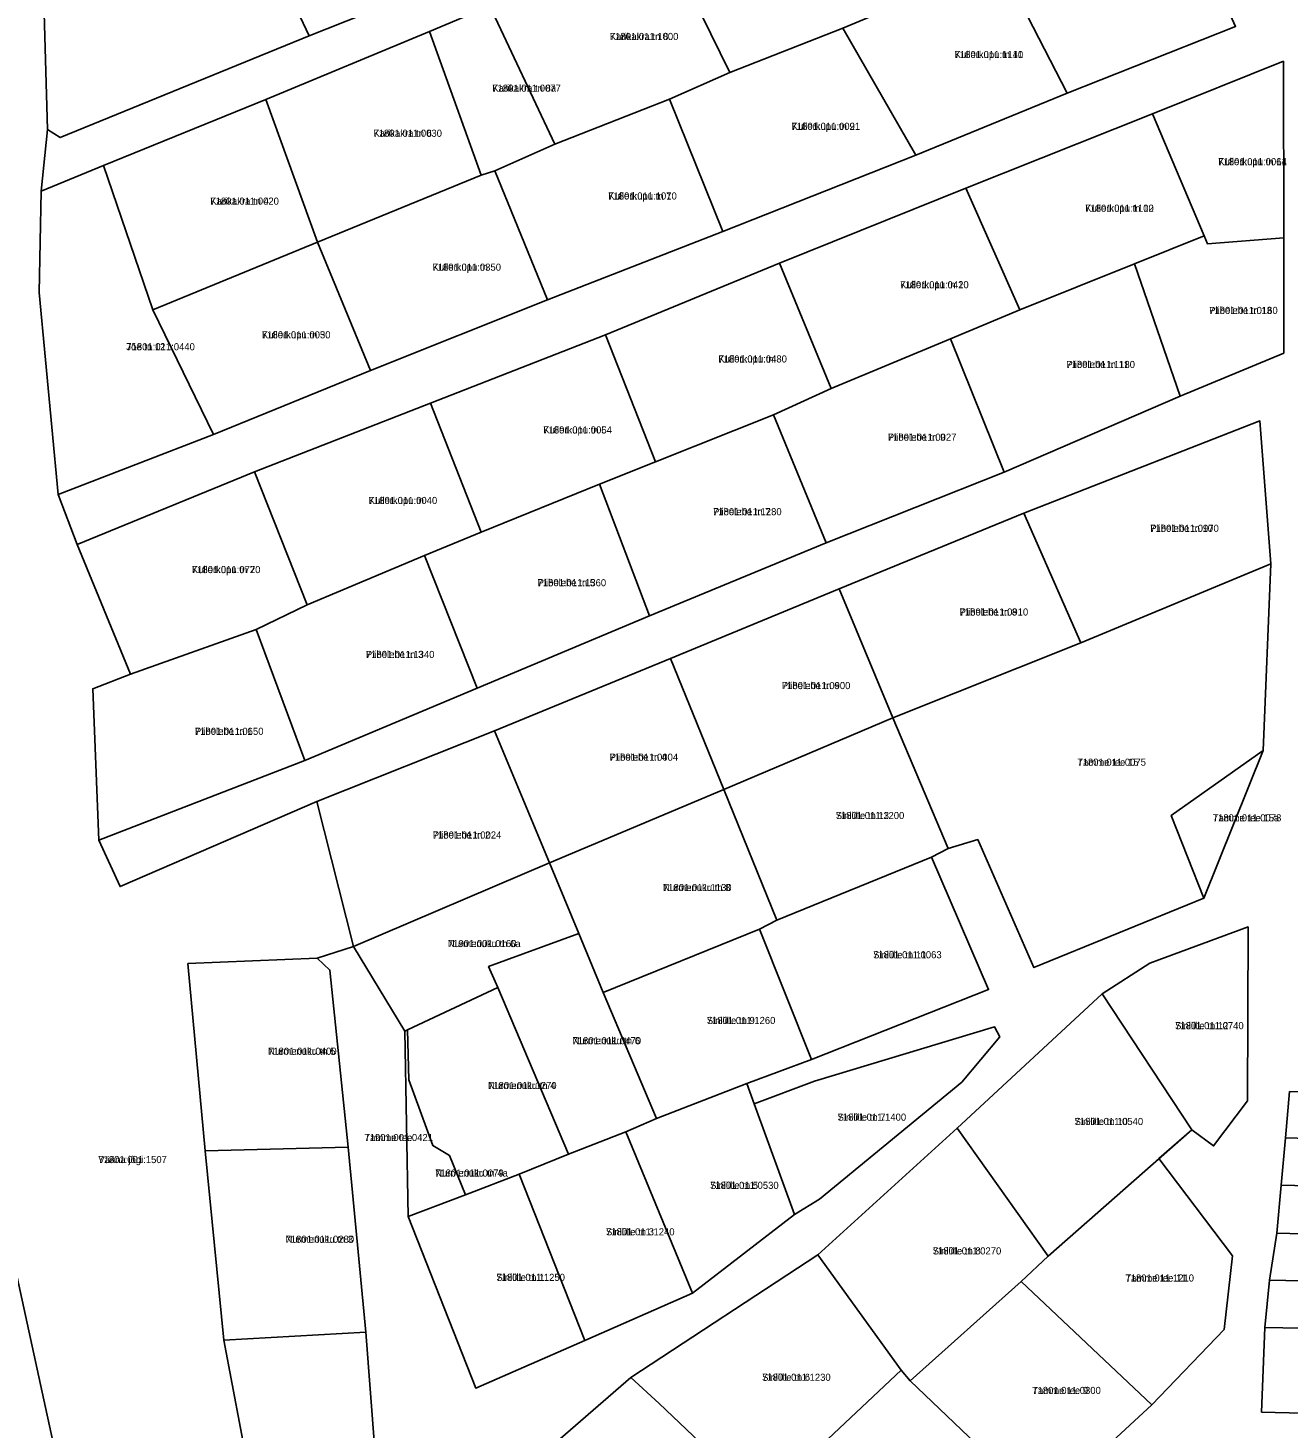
# Model space of a CAD drawing. Extents: x 529768 to 552006, y 6562269 to 6580975.
# Drawn here: x 537900.7 to 538167.2, y 6574495.4 to 6574791.4 of the extents above; entities that cross this region are included whole.
import ezdxf

# ---------------------------------------------------------------- set-up
doc = ezdxf.new("R2010")
doc.units = 0
for name, color, linetype in [('L_AADRESS', 7, 'Continuous'), ('PIIR', 7, 'Continuous'), ('TUNNUS', 7, 'Continuous')]:
    doc.layers.add(name, color=color, linetype=linetype)

msp = doc.modelspace()

# ---------------------------------------------------------------- linework, layer by layer
at = {"layer": 'PIIR'}
for points in [[(537946.52, 6574818.64), (537981.35, 6574832.85), (537995.22, 6574803.73), (537960.16, 6574789.77)], [(538085.22, 6574796.45), (538073.06, 6574791.35), (538049.15, 6574782), (538034.99, 6574810.89), (538071.56, 6574824.72)], [(538106.12, 6574805.6), (538120.62, 6574811.91), (538142.63, 6574821.49), (538156.07, 6574791.75), (538120.48, 6574777.61)], [(537960.16, 6574789.77), (537907.52, 6574768.22), (537904.83, 6574769.93), (537903.95, 6574801.98), (537911.06, 6574804.7), (537944.5, 6574817.88), (537946.52, 6574818.64)], [(538034.99, 6574810.89), (538049.15, 6574782), (538036.39, 6574776.37), (538012.14, 6574766.84), (537998.37, 6574795.99)], [(538088.44, 6574764.5), (538073.06, 6574791.35), (538085.22, 6574796.45), (538106.12, 6574805.6), (538120.48, 6574777.61)], [(537998.37, 6574795.99), (538012.14, 6574766.84), (537999.43, 6574761.17), (537996.55, 6574760.29), (537985.66, 6574790.65)], [(538088.44, 6574764.5), (538047.66, 6574748.39), (538036.39, 6574776.37), (538049.15, 6574782), (538073.06, 6574791.35)], [(537961.93, 6574746.14), (537951, 6574776.32), (537985.66, 6574790.65), (537996.55, 6574760.29)], [(538138.52, 6574773.26), (538166.19, 6574784.37), (538166.29, 6574747.06), (538150.16, 6574745.76), (538149.46, 6574747.46)], [(537927.1, 6574731.79), (537916.67, 6574762.36), (537951, 6574776.32), (537961.93, 6574746.14)], [(537999.43, 6574761.17), (538012.14, 6574766.84), (538036.39, 6574776.37), (538047.66, 6574748.39), (538010.58, 6574733.91)], [(538099.03, 6574757.55), (538138.52, 6574773.26), (538149.46, 6574747.46), (538134.72, 6574741.53), (538110.48, 6574731.84)], [(537903.06, 6574735.44), (537903.5, 6574756.9), (537916.67, 6574762.36), (537927.1, 6574731.79), (537939.95, 6574705.42), (537907.1, 6574692.78)], [(537973.17, 6574718.98), (537961.93, 6574746.14), (537996.55, 6574760.29), (537999.43, 6574761.17), (538010.58, 6574733.91)], [(538059.65, 6574741.7), (538099.03, 6574757.55), (538110.48, 6574731.84), (538095.8, 6574725.71), (538070.54, 6574715.19)], [(538144.39, 6574713.55), (538134.72, 6574741.53), (538149.46, 6574747.46), (538150.16, 6574745.76), (538166.29, 6574747.06), (538166.27, 6574722.66)], [(537939.95, 6574705.42), (537927.1, 6574731.79), (537961.93, 6574746.14), (537973.17, 6574718.98)], [(538033.39, 6574699.64), (538022.82, 6574726.53), (538059.65, 6574741.7), (538070.54, 6574715.19), (538058.39, 6574709.61)], [(538095.8, 6574725.71), (538110.48, 6574731.84), (538134.72, 6574741.53), (538144.39, 6574713.55), (538107.13, 6574697.48)], [(538033.39, 6574699.64), (538021.57, 6574694.92), (537996.56, 6574684.79), (537985.83, 6574712.06), (538022.82, 6574726.53)], [(538058.39, 6574709.61), (538070.54, 6574715.19), (538095.8, 6574725.71), (538107.13, 6574697.48), (538069.51, 6574682.55)], [(537959.78, 6574669.45), (537948.62, 6574697.53), (537985.83, 6574712.06), (537996.56, 6574684.79), (537984.6, 6574679.87)], [(538021.57, 6574694.92), (538033.39, 6574699.64), (538058.39, 6574709.61), (538069.51, 6574682.55), (538032.16, 6574667.12)], [(538111.33, 6574688.8), (538161.23, 6574708.32), (538163.52, 6574678.07), (538123.39, 6574661.39)], [(537911.11, 6574682.19), (537948.62, 6574697.53), (537959.78, 6574669.45), (537948.94, 6574664.21), (537922.42, 6574654.73)], [(537984.6, 6574679.87), (537996.56, 6574684.79), (538021.57, 6574694.92), (538032.16, 6574667.12), (537995.69, 6574651.8)], [(538072.26, 6574672.82), (538111.33, 6574688.8), (538123.39, 6574661.39), (538083.58, 6574645.52)], [(537948.94, 6574664.21), (537959.78, 6574669.45), (537984.6, 6574679.87), (537995.69, 6574651.8), (537959.25, 6574636.5)], [(538083.58, 6574645.52), (538123.39, 6574661.39), (538163.52, 6574678.07), (538161.94, 6574638.6), (538142.43, 6574624.87), (538149.4, 6574607.43), (538113.44, 6574592.72), (538101.55, 6574619.77), (538095.33, 6574617.87)], [(538036.56, 6574658.07), (538072.26, 6574672.82), (538083.58, 6574645.52), (538047.87, 6574630.38)], [(537914.42, 6574651.67), (537922.42, 6574654.73), (537948.94, 6574664.21), (537959.25, 6574636.5), (537915.72, 6574619.64)], [(537999.38, 6574642.8), (538036.56, 6574658.07), (538047.87, 6574630.38), (538010.97, 6574614.85)], [(538047.87, 6574630.38), (538083.58, 6574645.52), (538095.33, 6574617.87), (538091.8, 6574616.1), (538059.05, 6574602.74)], [(537961.83, 6574627.84), (537999.38, 6574642.8), (538010.97, 6574614.85), (537969.54, 6574597.19)], [(538142.43, 6574624.87), (538161.94, 6574638.6), (538149.4, 6574607.43)], [(538017.17, 6574599.89), (538010.97, 6574614.85), (538047.87, 6574630.38), (538059.05, 6574602.74), (538055.38, 6574600.81), (538022.32, 6574587.43)], [(537980.98, 6574579.52), (537980.41, 6574579.25), (537969.54, 6574597.19), (538010.97, 6574614.85), (538017.17, 6574599.89), (537998.11, 6574592.93), (538000.07, 6574588.52)], [(538091.8, 6574616.1), (538103.87, 6574588.05), (538066.43, 6574573.26), (538055.38, 6574600.81), (538059.05, 6574602.74)], [(537996.82, 6574478.82), (537997.54, 6574472.97), (537973.58, 6574445.13), (537997.53, 6574424.08), (538027.06, 6574397.05), (538048.62, 6574417.12), (538070.93, 6574438.07), (538093.3, 6574458.58), (538115.08, 6574478.77), (538138.41, 6574500.28), (538153.66, 6574516.15), (538155.46, 6574531.75), (538139.89, 6574552.36), (538146.85, 6574558.4), (538151.43, 6574555.01), (538158.6, 6574564.51), (538158.74, 6574601.33), (538137.96, 6574593.64), (538127.87, 6574587.14), (538097.2, 6574558.77), (538067.76, 6574531.97), (538028.22, 6574506.01)], [(537998.11, 6574592.93), (538017.17, 6574599.89), (538022.32, 6574587.43), (538033.62, 6574560.77), (538027.13, 6574558), (538015.02, 6574553.28), (538000.07, 6574588.52)], [(538022.32, 6574587.43), (538055.38, 6574600.81), (538066.43, 6574573.26), (538052.76, 6574568.17), (538033.62, 6574560.77)], [(538137.96, 6574593.64), (538158.74, 6574601.33), (538158.6, 6574564.51), (538151.43, 6574555.01), (538146.85, 6574558.4), (538127.87, 6574587.14)], [(537934.55, 6574593.57), (537961.9, 6574594.68), (537964.55, 6574592.18), (537968.41, 6574554.74), (537938.2, 6574553.94)], [(537980.98, 6574579.52), (538000.07, 6574588.52), (538015.02, 6574553.28), (538004.62, 6574549.06), (537993.21, 6574544.69), (537989.85, 6574553.01), (537986.35, 6574555.08), (537981.24, 6574569.01)], [(538097.2, 6574558.77), (538127.87, 6574587.14), (538146.85, 6574558.4), (538116.48, 6574531.71)], [(537980.41, 6574579.25), (537980.98, 6574579.52), (537981.24, 6574569.01), (537986.35, 6574555.08), (537989.85, 6574553.01), (537993.21, 6574544.69), (537981.08, 6574540.05)], [(538054.31, 6574563.89), (538067.05, 6574568.68), (538105.07, 6574580.21), (538106.22, 6574578.08), (538098.2, 6574568.52), (538068.07, 6574543.76), (538062.78, 6574540.47)], [(538027.13, 6574558), (538033.62, 6574560.77), (538052.76, 6574568.17), (538054.31, 6574563.89), (538062.78, 6574540.47), (538041.27, 6574523.83)], [(538167.5, 6574566.52), (538189.87, 6574565.98), (538209.2, 6574565.42), (538208.92, 6574555.53), (538166.62, 6574556.69)], [(538004.62, 6574549.06), (538015.03, 6574553.26), (538027.13, 6574558), (538041.27, 6574523.83), (538018.46, 6574513.87)], [(538067.76, 6574531.97), (538097.2, 6574558.77), (538116.48, 6574531.71), (538110.73, 6574526.33), (538087.27, 6574505.33), (538085.34, 6574507.58)], [(537938.2, 6574553.94), (537968.41, 6574554.74), (537972.15, 6574515.6), (537942.13, 6574513.92)], [(538208.92, 6574555.53), (538208.89, 6574554.47), (538208.66, 6574545.68), (538165.72, 6574546.67), (538166.62, 6574556.69)], [(538110.73, 6574526.33), (538116.48, 6574531.71), (538139.89, 6574552.36), (538155.46, 6574531.75), (538153.66, 6574516.15), (538138.41, 6574500.28)], [(537981.08, 6574540.05), (537993.21, 6574544.69), (538004.62, 6574549.06), (538018.46, 6574513.87), (537995.42, 6574503.81)], [(538208.66, 6574545.68), (538208.34, 6574535.42), (538164.83, 6574536.58), (538165.72, 6574546.67)], [(538163.23, 6574526.6), (538164.83, 6574536.58), (538208.34, 6574535.42), (538207.99, 6574525.72)], [(538028.22, 6574506.01), (538067.76, 6574531.97), (538085.34, 6574507.58), (538066.31, 6574489.65), (538067.55, 6574488.41), (538064.58, 6574485.79), (538057.15, 6574478.7), (538034.16, 6574500.56)], [(538087.27, 6574505.33), (538110.73, 6574526.33), (538138.41, 6574500.28), (538115.08, 6574478.77)], [(538162.24, 6574516.63), (538163.23, 6574526.6), (538207.99, 6574525.72), (538207.6, 6574515.74)], [(537942.13, 6574513.92), (537972.15, 6574515.6), (537976, 6574465.87), (537963.82, 6574455.16), (537950.92, 6574467.42)], [(538207.24, 6574503.12), (538208.48, 6574502.05), (538205.17, 6574497.62), (538161.6, 6574498.73), (538162.24, 6574516.63), (538207.6, 6574515.74)], [(538066.31, 6574489.65), (538085.34, 6574507.58), (538087.27, 6574505.33), (538115.08, 6574478.77), (538093.3, 6574458.58), (538064.58, 6574485.79), (538067.55, 6574488.41)], [(537996.82, 6574478.82), (538028.22, 6574506.01), (538034.16, 6574500.56), (538057.15, 6574478.7), (538042.38, 6574464.77), (538026.52, 6574450.97), (537997.54, 6574472.97)]]:
    msp.add_lwpolyline(points, close=True, dxfattribs=at)
for points in [[(537877.44, 6574804.07), (537877.38, 6574790.27), (537879.6, 6574679.21), (537880.42, 6574620.55), (537883.61, 6574583.23), (537894.34, 6574545.71), (537908.44, 6574481.23)], [(537954.55, 6574169.98), (537951.1, 6574224.38), (537959.6, 6574242.27), (537930.27, 6574387.38), (537908.44, 6574481.23), (537894.34, 6574545.71), (537883.61, 6574583.23), (537880.42, 6574620.55), (537879.6, 6574679.21), (537877.38, 6574790.27), (537877.44, 6574804.07)], [(537998.37, 6574795.99), (537985.66, 6574790.65), (537951, 6574776.32), (537916.67, 6574762.36), (537903.5, 6574756.9), (537904.83, 6574769.93), (537907.52, 6574768.22), (537960.16, 6574789.77), (537995.22, 6574803.73)], [(537903.95, 6574801.98), (537904.83, 6574769.93), (537903.5, 6574756.9), (537903.06, 6574735.44), (537907.1, 6574692.78), (537911.11, 6574682.19), (537922.42, 6574654.73), (537914.42, 6574651.67), (537915.72, 6574619.64), (537920.2, 6574609.84), (537961.83, 6574627.84), (537969.54, 6574597.19), (537961.9, 6574594.68), (537934.55, 6574593.57), (537938.2, 6574553.94), (537942.13, 6574513.92), (537950.92, 6574467.42)], [(537976, 6574465.87), (537972.15, 6574515.6), (537968.41, 6574554.74), (537964.55, 6574592.18), (537961.9, 6574594.68), (537969.54, 6574597.19), (537980.41, 6574579.25), (537981.08, 6574540.05), (537995.42, 6574503.81), (538018.46, 6574513.87), (538041.27, 6574523.83), (538062.78, 6574540.47), (538068.07, 6574543.76), (538098.2, 6574568.52), (538106.22, 6574578.08), (538105.07, 6574580.21), (538067.05, 6574568.68), (538054.31, 6574563.89), (538052.76, 6574568.17), (538066.43, 6574573.26), (538103.87, 6574588.05), (538091.8, 6574616.1), (538095.33, 6574617.87), (538101.55, 6574619.77), (538113.44, 6574592.72), (538149.4, 6574607.43), (538161.94, 6574638.6), (538163.52, 6574678.07), (538161.23, 6574708.32), (538111.33, 6574688.8), (538072.26, 6574672.82), (538036.56, 6574658.07), (537999.38, 6574642.8), (537961.83, 6574627.84), (537920.2, 6574609.84), (537915.72, 6574619.64), (537959.25, 6574636.5), (537995.69, 6574651.8), (538032.16, 6574667.12), (538069.51, 6574682.55), (538107.13, 6574697.48), (538144.39, 6574713.55), (538166.27, 6574722.66), (538166.29, 6574747.06), (538166.19, 6574784.37), (538138.52, 6574773.26), (538099.03, 6574757.55), (538059.65, 6574741.7), (538022.82, 6574726.53), (537985.83, 6574712.06), (537948.62, 6574697.53), (537911.11, 6574682.19), (537907.1, 6574692.78), (537939.95, 6574705.42), (537973.17, 6574718.98), (538010.58, 6574733.91), (538047.66, 6574748.39), (538088.44, 6574764.5), (538120.48, 6574777.61), (538156.07, 6574791.75)], [(538167.5, 6574566.52), (538166.62, 6574556.69), (538165.72, 6574546.67), (538164.83, 6574536.58), (538163.23, 6574526.6), (538162.24, 6574516.63), (538161.6, 6574498.73), (538205.17, 6574497.62)]]:
    msp.add_lwpolyline(points, dxfattribs=at)

# ---------------------------------------------------------------- texts
at = {"layer": 'L_AADRESS'}
for s, p in [('Karikakra tn 8', (538023.76, 6574788.87)), ('Kullerkupu tn 11', (538096.67, 6574785.05)), ('Karikakra tn 8a', (537998.9, 6574777.94)), ('Kullerkupu tn 9', (538062.19, 6574769.87)), ('Karikakra tn 6', (537973.76, 6574768.4)), ('Kullerkupu tn 14', (538152.41, 6574762.39)), ('Karikakra tn 4', (537939.28, 6574754.05)), ('Kullerkupu tn 7', (538023.42, 6574755.14)), ('Kullerkupu tn 12', (538124.28, 6574752.55)), ('Kullerkupu tn 5', (537986.25, 6574740.08)), ('Kullerkupu tn 10', (538085.15, 6574736.37)), ('Piibelehe tn 13', (538150.5, 6574730.94)), ('Kullerkupu tn 3', (537950.19, 6574725.78)), ('Jõe tn 12', (537921.51, 6574723.26)), ('Kullerkupu tn 8', (538046.71, 6574720.67)), ('Piibelehe tn 11', (538120.31, 6574719.51)), ('Kullerkupu tn 6', (538009.69, 6574705.66)), ('Piibelehe tn 9', (538082.55, 6574704.13)), ('Kullerkupu tn 4', (537972.76, 6574690.75)), ('Piibelehe tn 7', (538045.59, 6574688.37)), ('Piibelehe tn 10', (538138.04, 6574684.86)), ('Kullerkupu tn 2', (537935.37, 6574676.13)), ('Piibelehe tn 5', (538008.48, 6574673.36)), ('Piibelehe tn 8', (538097.73, 6574667.16)), ('Piibelehe tn 3', (537972.17, 6574658.19)), ('Piibelehe tn 6', (538060.13, 6574651.6)), ('Piibelehe tn 1', (537936.02, 6574641.93)), ('Piibelehe tn 4', (538023.7, 6574636.46)), ('Tamme tee 15', (538122.63, 6574635.4)), ('Sinilille tn 13', (538071.53, 6574624.13)), ('Tamme tee 15a', (538151.26, 6574623.63)), ('Piibelehe tn 2', (537986.32, 6574620)), ('Nurmenuku tn 8', (538035, 6574608.9)), ('Nurmenuku tn 6a', (537989.51, 6574597.05)), ('Sinilille tn 11', (538079.43, 6574594.68)), ('Sinilille tn 9', (538044.27, 6574580.79)), ('Sinilille tn 12', (538143.3, 6574579.69)), ('Nurmenuku tn 6', (538015.86, 6574576.51)), ('Nurmenuku tn 5', (537951.48, 6574574.27)), ('Nurmenuku tn 4', (537998, 6574567.03)), ('Sinilille tn 7', (538071.92, 6574560.34)), ('Sinilille tn 10', (538122.04, 6574559.43)), ('Tamme tee', (537971.86, 6574556.03)), ('Vääna jõgi', (537915.59, 6574551.37)), ('Nurmenuku tn 4a', (537986.81, 6574548.52)), ('Sinilille tn 5', (538044.96, 6574545.92)), ('Sinilille tn 3', (538022.95, 6574536.09)), ('Nurmenuku tn 3', (537955.18, 6574534.52)), ('Sinilille tn 8', (538092.04, 6574532.05)), ('Sinilille tn 1', (537999.77, 6574526.46)), ('Tamme tee 11', (538132.79, 6574526.32)), ('Sinilille tn 6', (538055.96, 6574505.33)), ('Tamme tee 9', (538113.09, 6574502.55))]:
    msp.add_text(s, height=1.5, dxfattribs=at).set_placement(p)
at = {"layer": 'TUNNUS'}
for s, p in [('71801:011:1000', (538023.76, 6574788.87)), ('71801:011:1140', (538096.67, 6574785.05)), ('71801:011:0077', (537998.9, 6574777.94)), ('71801:011:0021', (538062.19, 6574769.87)), ('71801:011:0030', (537973.76, 6574768.4)), ('71801:011:0061', (538152.41, 6574762.39)), ('71801:011:0020', (537939.28, 6574754.05)), ('71801:011:1010', (538023.42, 6574755.14)), ('71801:011:1100', (538124.28, 6574752.55)), ('71801:011:0350', (537986.25, 6574740.08)), ('71801:011:0420', (538085.15, 6574736.37)), ('71801:011:0160', (538150.5, 6574730.94)), ('71801:011:0050', (537950.19, 6574725.78)), ('71801:011:0440', (537921.51, 6574723.26)), ('71801:011:0430', (538046.71, 6574720.67)), ('71801:011:1180', (538120.31, 6574719.51)), ('71801:011:0054', (538009.69, 6574705.66)), ('71801:011:0027', (538082.55, 6574704.13)), ('71801:011:0040', (537972.76, 6574690.75)), ('71801:011:1280', (538045.59, 6574688.37)), ('71801:011:0970', (538138.04, 6574684.86)), ('71801:011:0770', (537935.37, 6574676.13)), ('71801:011:1360', (538008.48, 6574673.36)), ('71801:011:0910', (538097.73, 6574667.16)), ('71801:011:1340', (537972.17, 6574658.19)), ('71801:011:0900', (538060.13, 6574651.6)), ('71801:011:0650', (537936.02, 6574641.93)), ('71801:011:0004', (538023.7, 6574636.46)), ('71801:011:0075', (538122.63, 6574635.4)), ('71801:011:1200', (538071.53, 6574624.13)), ('71801:011:0078', (538151.26, 6574623.63)), ('71801:011:0024', (537986.32, 6574620)), ('71801:011:1130', (538035, 6574608.9)), ('71901:001:0160', (537989.51, 6574597.05)), ('71801:011:0063', (538079.43, 6574594.68)), ('71801:011:1260', (538044.27, 6574580.79)), ('71801:011:0740', (538143.3, 6574579.69)), ('71801:011:0470', (538015.86, 6574576.51)), ('71801:011:0400', (537951.48, 6574574.27)), ('71801:011:1270', (537998, 6574567.03)), ('71801:011:1400', (538071.92, 6574560.34)), ('71801:011:0540', (538122.04, 6574559.43)), ('71901:001:0421', (537971.86, 6574556.03)), ('71801:001:1507', (537915.59, 6574551.37)), ('71801:011:0079', (537986.81, 6574548.52)), ('71801:011:0530', (538044.96, 6574545.92)), ('71801:011:1240', (538022.95, 6574536.09)), ('71801:011:0280', (537955.18, 6574534.52)), ('71801:011:0270', (538092.04, 6574532.05)), ('71801:011:1250', (537999.77, 6574526.46)), ('71801:011:1210', (538132.79, 6574526.32)), ('71801:011:1230', (538055.96, 6574505.33)), ('71801:011:0300', (538113.09, 6574502.55))]:
    msp.add_text(s, height=1.5, dxfattribs=at).set_placement(p)

doc.saveas('drawing.dxf')
